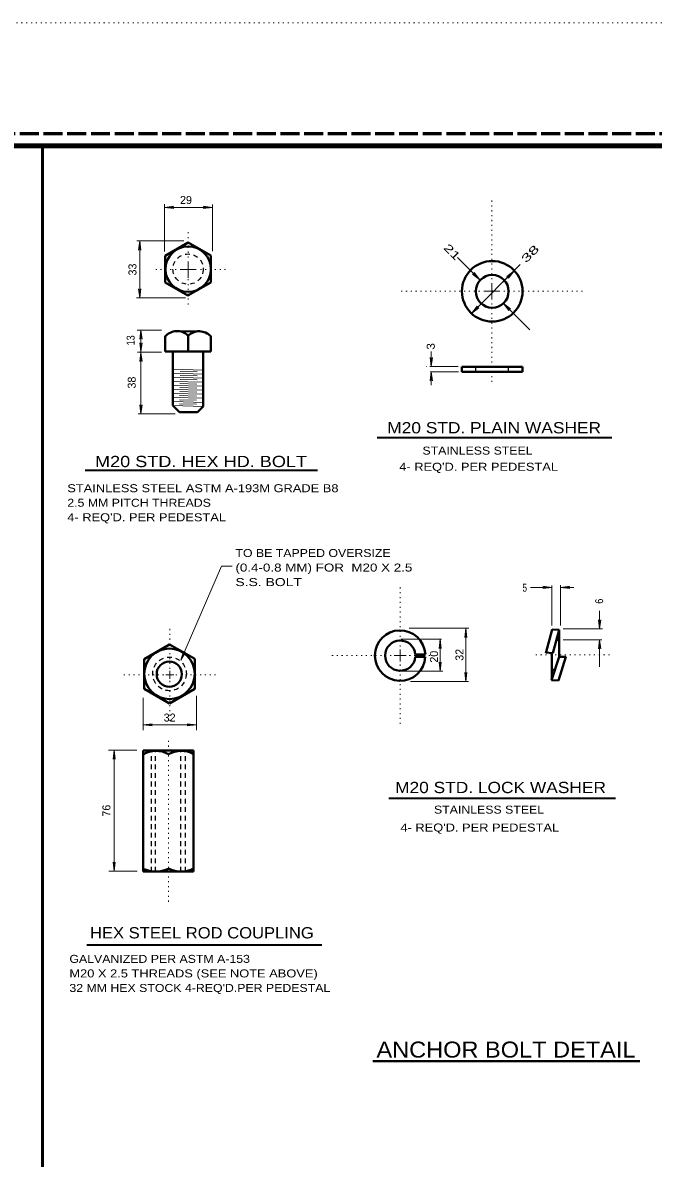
# Model space of a CAD drawing. Extents: x 312583 to 312854, y 144419 to 144597.
# Drawn here: x 312706.2 to 312766.1, y 144488.9 to 144596.8 of the extents above; entities that cross this region are included whole.
import ezdxf
from ezdxf.enums import TextEntityAlignment as Align

# ---------------------------------------------------------------- set-up
doc = ezdxf.new("R2010")
doc.units = 0
doc.header["$LTSCALE"] = 0.3
doc.header["$PDMODE"] = 32
doc.header["$PDSIZE"] = 0.15
for name, pattern in [('DOTTED', [1.5, 0.3, -1.2]), ('LONG_DASHED', [7.5, 6, -1.5]), ('SHORT_DASHED', [2.7, 1.5, -1.2])]:
    doc.linetypes.add(name, pattern=pattern)
for name, color, linetype, lineweight in [('1', 7, 'Continuous', 40), ('2', 7, 'Continuous', 13), ('62', 7, 'DOTTED', 13), ('63', 7, 'LONG_DASHED', 60)]:
    doc.layers.add(name, color=color, linetype=linetype, lineweight=lineweight)

msp = doc.modelspace()

# ---------------------------------------------------------------- linework, layer by layer
at = {"layer": '1', "linetype": 'DOTTED', "lineweight": 13}
for p, q in [((312721.9324, 144574.485), (312721.9324, 144577.176)), ((312720.7824, 144573.335), (312718.536, 144573.335)), ((312723.0824, 144573.335), (312725.7734, 144573.335)), ((312721.9324, 144572.4303), (312721.9324, 144569.7317)), ((312754.9401, 144536.7493), (312761.9935, 144536.7493)), ((312720.0558, 144513.3121), (312720.0558, 144528.8908))]:
    msp.add_line(p, q, dxfattribs=at)
at = {"layer": '1'}
for p, q in [((312719.7474, 144574.646), (312721.9324, 144575.9033)), ((312724.0714, 144574.669), (312721.9324, 144575.9033)), ((312719.7474, 144574.646), (312719.7474, 144572.1083)), ((312724.0714, 144574.669), (312724.0714, 144572.116)), ((312721.9094, 144570.8663), (312719.7474, 144572.1083)), ((312721.9094, 144570.8663), (312724.0714, 144572.116)), ((312722.9137, 144567.493), (312720.8284, 144567.47)), ((312719.7474, 144566.9947), (312719.7474, 144565.561)), ((312721.9247, 144565.5763), (312721.9247, 144567.056)), ((312724.0714, 144567.01), (312724.0714, 144565.561)), ((312719.7474, 144565.561), (312724.0714, 144565.561)), ((312720.4834, 144560.4243), (312720.4834, 144565.561)), ((312723.3584, 144560.3477), (312723.3584, 144565.561)), ((312747.9235, 144563.6439), (312747.9235, 144564.1193)), ((312747.9235, 144564.1193), (312753.6735, 144564.1193)), ((312753.6735, 144563.6439), (312753.6735, 144564.1193)), ((312747.9235, 144563.6439), (312753.6735, 144563.6439)), ((312720.4834, 144560.9993), (312720.4527, 144560.9687)), ((312720.4834, 144560.4243), (312721.0967, 144559.811)), ((312721.0967, 144559.811), (312722.8217, 144559.811)), ((312723.3584, 144560.3477), (312722.8217, 144559.811)), ((312756.5655, 144536.9179), (312757.1711, 144539.1259)), ((312757.1711, 144536.6036), (312757.1711, 144539.1259)), ((312756.9028, 144538.1906), (312757.1711, 144538.1906)), ((312717.7405, 144536.3428), (312720.1632, 144537.7458)), ((312722.5475, 144536.3658), (312720.1632, 144537.7458)), ((312755.8985, 144536.9639), (312756.5655, 144536.9179)), ((312717.7405, 144536.3428), (312717.7405, 144533.5215)), ((312722.5475, 144536.3658), (312722.5475, 144533.5291)), ((312744.4445, 144536.5576), (312743.4938, 144536.5576)), ((312744.4521, 144536.7953), (312743.5015, 144536.7953)), ((312756.4505, 144534.3573), (312756.4505, 144536.8566)), ((312757.1098, 144534.3036), (312757.7921, 144536.5806)), ((312756.4505, 144535.3616), (312756.7571, 144535.3386)), ((312756.4351, 144534.3496), (312757.1098, 144534.3036)), ((312720.1402, 144532.1415), (312717.7405, 144533.5215)), ((312720.1402, 144532.1415), (312722.5475, 144533.5291)), ((312717.6408, 144527.6641), (312717.6408, 144516.1641)), ((312717.6408, 144527.6641), (312722.4478, 144527.6641)), ((312722.4478, 144527.6641), (312722.4478, 144516.1641)), ((312717.6408, 144516.1641), (312722.4478, 144516.1641)), ((312739.4597, 144498.178), (312764.8218, 144498.178))]:
    msp.add_line(p, q, dxfattribs=at)
at = {"layer": '1', "lineweight": 13}
for p, q in [((312721.9324, 144573.335), (312721.9324, 144574.1017)), ((312721.9324, 144573.335), (312721.1657, 144573.335)), ((312721.9324, 144573.335), (312721.9324, 144572.5683)), ((312721.9324, 144573.335), (312722.699, 144573.335)), ((312744.5808, 144564.1423), (312744.5731, 144564.1423)), ((312720.468, 144563.491), (312723.3737, 144563.4143)), ((312720.4757, 144563.8743), (312723.3507, 144563.7977)), ((312720.491, 144563.1077), (312723.343, 144563.031)), ((312721.158, 144562.9007), (312722.768, 144562.8547)), ((312721.1657, 144563.284), (312722.7757, 144563.238)), ((312721.1734, 144563.6673), (312722.7834, 144563.6213)), ((312720.4757, 144562.7243), (312723.343, 144562.6477)), ((312720.5294, 144561.9577), (312723.3507, 144561.881)), ((312720.537, 144562.341), (312723.3584, 144562.2643)), ((312721.1274, 144561.7507), (312722.7374, 144561.7047)), ((312721.135, 144562.134), (312722.745, 144562.088)), ((312721.1427, 144562.5173), (312722.7527, 144562.4713)), ((312720.4987, 144560.8077), (312723.3737, 144560.731)), ((312720.5064, 144561.191), (312723.3814, 144561.1143)), ((312720.514, 144561.5743), (312723.389, 144561.4977)), ((312721.1044, 144560.984), (312722.7144, 144560.938)), ((312721.112, 144561.3673), (312722.722, 144561.3213)), ((312720.4834, 144560.4243), (312723.3584, 144560.3477)), ((312721.0967, 144560.6007), (312722.7067, 144560.5547)), ((312721.2442, 144536.2355), (312721.4801, 144537.0747)), ((312721.2442, 144536.2355), (312721.6767, 144536.9951)), ((312721.4801, 144537.0747), (312721.4735, 144536.7814)), ((312721.6767, 144536.9951), (312721.4735, 144536.7814))]:
    msp.add_line(p, q, dxfattribs=at)
at = {"layer": '1', "linetype": 'SHORT_DASHED', "lineweight": 25}
for p, q in [((312721.9247, 144570.8663), (312721.9017, 144570.874)), ((312749.2421, 144563.6439), (312749.2421, 144564.1193)), ((312752.3548, 144563.6439), (312752.3548, 144564.1193)), ((312720.1555, 144532.1415), (312720.1325, 144532.1568)), ((312718.4535, 144516.1641), (312718.4535, 144527.6641)), ((312718.8292, 144516.1641), (312718.8292, 144527.6641)), ((312721.2365, 144516.1641), (312721.2365, 144527.6641)), ((312721.6658, 144516.1641), (312721.6658, 144527.6641))]:
    msp.add_line(p, q, dxfattribs=at)
at = {"layer": '1', "lineweight": 35}
for p, q in [((312739.8748, 144557.4033), (312762.1627, 144557.4033)), ((312712.1367, 144554.2771), (312734.2119, 144554.2771)), ((312740.9745, 144523.1409), (312762.5182, 144523.1409)), ((312712.2913, 144509.2184), (312734.6146, 144509.2184))]:
    msp.add_line(p, q, dxfattribs=at)
at = {"layer": '1', "lineweight": 158}
msp.add_lwpolyline([(312616.5, 144423.1446), (312616.5, 144585.0846), (312849, 144585.0846)], dxfattribs=at)
at = {"layer": '1'}
for points in [[(312755.8908, 144536.9179), (312756.5041, 144539.1566), (312757.1711, 144539.1259)], [(312756.4351, 144534.3496), (312757.1635, 144536.5729), (312757.8228, 144536.5576)]]:
    msp.add_lwpolyline(points, dxfattribs=at)
for centre, radius in [((312721.9285, 144573.3848), 2.1562), ((312750.8023, 144571.2761), 2.875), ((312750.8023, 144571.2761), 1.5573), ((312720.1478, 144534.9513), 2.3958), ((312720.1325, 144534.9168), 1.1979)]:
    msp.add_circle(centre, radius, dxfattribs=at)
at = {"layer": '1', "linetype": 'SHORT_DASHED', "lineweight": 25}
for centre, radius in [((312721.9209, 144573.3848), 1.4375), ((312720.1546, 144534.9419), 1.5972)]:
    msp.add_circle(centre, radius, dxfattribs=at)
at = {"layer": '1'}
for centre, radius, start, end in [((312720.8664, 144566.0408), 1.4637, 43.91386, 141.2822), ((312722.9716, 144565.9716), 1.5099, 43.25022, 134.09484), ((312742.0563, 144536.6803), 2.3958, 2.66087, 356.97276), ((312742.064, 144536.6803), 1.4375, 4.43385, 354.95755), ((312718.8693, 144525.2575), 2.3801, 60.20304, 121.07217), ((312721.251, 144525.1939), 2.4434, 60.98127, 119.38719), ((312718.8464, 144518.9146), 2.7507, 243.73896, 296.26105), ((312721.2448, 144518.7408), 2.5691, 242.81753, 297.92176)]:
    msp.add_arc(centre, radius, start, end, dxfattribs=at)
at = {"layer": '2', "lineweight": 53}
msp.add_line((312708.0873, 144423.0846), (312708.0873, 144585.0846), dxfattribs=at)
at = {"layer": '2', "linetype": 'DOTTED'}
for p, q in [((312750.7601, 144572.4299), (312750.7601, 144580.0966)), ((312749.6101, 144571.2799), (312741.9435, 144571.2799)), ((312751.9101, 144571.2799), (312759.5768, 144571.2799)), ((312750.7601, 144570.1299), (312750.7601, 144562.4633)), ((312742.0678, 144537.5466), (312742.0678, 144543.2966)), ((312720.1785, 144535.4305), (312720.1785, 144539.2638)), ((312741.2015, 144536.6879), (312735.4515, 144536.6879)), ((312742.9265, 144536.6879), (312745.2341, 144536.6879)), ((312719.6035, 144534.8478), (312715.7702, 144534.8478)), ((312720.7535, 144534.8478), (312724.5868, 144534.8478)), ((312742.0678, 144535.8216), (312742.0678, 144530.0716)), ((312720.1785, 144534.2728), (312720.1785, 144530.4395))]:
    msp.add_line(p, q, dxfattribs=at)
at = {"layer": '2'}
for p, q in [((312719.686, 144575.0447), (312719.686, 144579.5603)), ((312719.686, 144579.246), (312720.5524, 144579.3533)), ((312719.686, 144579.246), (312724.2247, 144579.246)), ((312719.686, 144579.246), (312720.5524, 144579.1387)), ((312720.5524, 144579.3533), (312720.2764, 144579.246)), ((312720.5524, 144579.1387), (312720.2764, 144579.246)), ((312723.3584, 144579.3533), (312723.6344, 144579.246)), ((312724.2247, 144579.246), (312723.3584, 144579.3533)), ((312723.3584, 144579.3533), (312723.6344, 144579.246)), ((312724.2247, 144579.246), (312723.3584, 144579.3533)), ((312723.3584, 144579.1387), (312723.6344, 144579.246)), ((312724.2247, 144579.246), (312723.3584, 144579.1387)), ((312723.3584, 144579.1387), (312723.6344, 144579.246)), ((312724.2247, 144579.246), (312723.3584, 144579.1387)), ((312724.2247, 144575.0753), (312724.2247, 144579.5067)), ((312717.064, 144576.0567), (312721.526, 144576.0567)), ((312717.3247, 144576.0567), (312717.2174, 144575.1903)), ((312717.3247, 144570.6593), (312717.3247, 144576.0567)), ((312717.3247, 144576.0567), (312717.432, 144575.1903)), ((312717.2174, 144575.1903), (312717.3247, 144575.4663)), ((312717.432, 144575.1903), (312717.3247, 144575.4663)), ((312749.6255, 144572.3609), (312747.4941, 144574.4923)), ((312753.4588, 144573.8099), (312748.8281, 144569.1793)), ((312748.9355, 144572.8976), (312749.2115, 144572.7826)), ((312749.6255, 144572.3609), (312748.9355, 144572.8976)), ((312749.0888, 144573.0509), (312749.2115, 144572.7826)), ((312749.6255, 144572.3609), (312749.0888, 144573.0509)), ((312752.8761, 144573.2273), (312751.8028, 144572.1539)), ((312752.8761, 144573.2273), (312752.1861, 144572.6906)), ((312752.1861, 144572.6906), (312752.4545, 144572.8056)), ((312752.8761, 144573.2273), (312752.3395, 144572.5373)), ((312752.3395, 144572.5373), (312752.4545, 144572.8056)), ((312717.2174, 144571.5257), (312717.3247, 144571.2497)), ((312717.3247, 144570.6593), (312717.2174, 144571.5257)), ((312717.432, 144571.5257), (312717.3247, 144571.2497)), ((312717.3247, 144570.6593), (312717.432, 144571.5257)), ((312750.7601, 144571.2799), (312750.7601, 144572.0466)), ((312717.0104, 144570.6593), (312721.6794, 144570.6593)), ((312750.7601, 144571.2799), (312749.9935, 144571.2799)), ((312750.7601, 144571.2799), (312750.7601, 144570.5133)), ((312750.7601, 144571.2799), (312751.5268, 144571.2799)), ((312748.8281, 144569.1793), (312749.3648, 144569.8693)), ((312748.8281, 144569.1793), (312749.5181, 144569.7159)), ((312749.3648, 144569.8693), (312749.2421, 144569.5933)), ((312749.5181, 144569.7159), (312749.2421, 144569.5933)), ((312754.3635, 144567.6306), (312751.8488, 144570.1376)), ((312751.8488, 144570.1376), (312752.3855, 144569.4476)), ((312751.8488, 144570.1376), (312752.5388, 144569.6009)), ((312752.3855, 144569.4476), (312752.2705, 144569.7236)), ((312752.5388, 144569.6009), (312752.2705, 144569.7236)), ((312717.0717, 144567.585), (312719.3947, 144567.585)), ((312717.4397, 144567.585), (312717.3324, 144566.7187)), ((312717.4397, 144567.585), (312717.547, 144566.7187)), ((312717.4397, 144565.515), (312717.4397, 144567.585)), ((312717.3324, 144566.7187), (312717.4397, 144566.9947)), ((312717.3324, 144566.3813), (312717.4397, 144566.1053)), ((312717.4397, 144565.515), (312717.3324, 144566.3813)), ((312717.547, 144566.7187), (312717.4397, 144566.9947)), ((312717.547, 144566.3813), (312717.4397, 144566.1053)), ((312717.4397, 144565.515), (312717.547, 144566.3813)), ((312717.11, 144565.4843), (312719.3947, 144565.4843)), ((312717.4397, 144565.469), (312717.3324, 144564.6027)), ((312717.4397, 144559.6423), (312717.4397, 144565.469)), ((312717.4397, 144565.469), (312717.547, 144564.6027)), ((312744.9105, 144565.0009), (312745.0178, 144564.7249)), ((312745.0178, 144564.1346), (312744.9105, 144565.0009)), ((312745.0178, 144565.5453), (312745.0178, 144564.1346)), ((312745.1251, 144565.0009), (312745.0178, 144564.7249)), ((312745.0178, 144564.1346), (312745.1251, 144565.0009)), ((312717.3324, 144564.6027), (312717.4397, 144564.8787)), ((312717.547, 144564.6027), (312717.4397, 144564.8787)), ((312747.5631, 144564.1423), (312744.8875, 144564.1423)), ((312745.0178, 144563.6363), (312744.9105, 144562.7699)), ((312744.9105, 144562.7699), (312745.0178, 144563.0459)), ((312747.5861, 144563.6363), (312744.9181, 144563.6363)), ((312745.0178, 144563.6363), (312745.0178, 144562.3789)), ((312745.0178, 144563.6363), (312745.1251, 144562.7699)), ((312745.1251, 144562.7699), (312745.0178, 144563.0459)), ((312717.1867, 144559.6423), (312720.7057, 144559.6423)), ((312717.3324, 144560.5087), (312717.4397, 144560.2327)), ((312717.4397, 144559.6423), (312717.3324, 144560.5087)), ((312717.547, 144560.5087), (312717.4397, 144560.2327)), ((312717.4397, 144559.6423), (312717.547, 144560.5087)), ((312725.0965, 144545.1776), (312721.2442, 144536.2355)), ((312726.1085, 144545.1776), (312725.0965, 144545.1776)), ((312756.4658, 144543.1586), (312754.4493, 144543.1586)), ((312755.5995, 144543.2659), (312755.8755, 144543.1586)), ((312756.4658, 144543.1586), (312755.5995, 144543.2659)), ((312755.5995, 144543.0513), (312755.8755, 144543.1586)), ((312756.4658, 144543.1586), (312755.5995, 144543.0513)), ((312756.4581, 144539.5399), (312756.4581, 144543.3273)), ((312757.2861, 144539.5399), (312757.2861, 144543.3656)), ((312757.2938, 144543.1586), (312758.1601, 144543.2659)), ((312758.5665, 144543.1586), (312757.2938, 144543.1586)), ((312757.2938, 144543.1586), (312758.1601, 144543.0513)), ((312758.1601, 144543.2659), (312757.8841, 144543.1586)), ((312758.1601, 144543.0513), (312757.8841, 144543.1586)), ((312760.9968, 144539.2103), (312760.9968, 144540.9384)), ((312748.5768, 144539.2793), (312742.9111, 144539.2793)), ((312748.2931, 144539.2793), (312748.1858, 144538.4129)), ((312748.2931, 144534.2193), (312748.2931, 144539.2793)), ((312748.2931, 144539.2793), (312748.4005, 144538.4129)), ((312761.2881, 144539.2103), (312757.5315, 144539.2103)), ((312760.8895, 144540.0766), (312760.9968, 144539.8006)), ((312760.9968, 144539.2103), (312760.8895, 144540.0766)), ((312760.8895, 144540.0766), (312760.9968, 144539.8006)), ((312760.9968, 144539.2103), (312760.8895, 144540.0766)), ((312761.1041, 144540.0766), (312760.9968, 144539.8006)), ((312760.9968, 144539.2103), (312761.1041, 144540.0766)), ((312761.1041, 144540.0766), (312760.9968, 144539.8006)), ((312760.9968, 144539.2103), (312761.1041, 144540.0766)), ((312745.9931, 144538.2289), (312742.1291, 144538.2289)), ((312745.8551, 144538.2289), (312745.7478, 144537.3626)), ((312745.8551, 144535.1929), (312745.8551, 144538.2289)), ((312745.8551, 144538.2289), (312745.9625, 144537.3626)), ((312748.1858, 144538.4129), (312748.2931, 144538.6889)), ((312748.4005, 144538.4129), (312748.2931, 144538.6889)), ((312761.1961, 144538.1829), (312757.5315, 144538.1829)), ((312760.9968, 144538.1829), (312760.8895, 144537.3166)), ((312760.9968, 144535.6299), (312760.9968, 144538.1829)), ((312760.9968, 144538.1829), (312761.1041, 144537.3166)), ((312742.0678, 144536.6879), (312742.0678, 144537.2629)), ((312745.7478, 144537.3626), (312745.8551, 144537.6386)), ((312745.9625, 144537.3626), (312745.8551, 144537.6386)), ((312760.8895, 144537.3166), (312760.9968, 144537.5926)), ((312761.1041, 144537.3166), (312760.9968, 144537.5926)), ((312742.0678, 144536.6879), (312741.4851, 144536.6879)), ((312742.0678, 144536.6879), (312742.6428, 144536.6879)), ((312742.0678, 144536.6879), (312742.0678, 144536.1129)), ((312745.7478, 144536.0593), (312745.8551, 144535.7833)), ((312745.8551, 144535.1929), (312745.7478, 144536.0593)), ((312745.9625, 144536.0593), (312745.8551, 144535.7833)), ((312745.8551, 144535.1929), (312745.9625, 144536.0593)), ((312720.1785, 144534.8478), (312719.7952, 144534.8478)), ((312720.1785, 144534.8478), (312720.1785, 144535.2388)), ((312720.1785, 144534.8478), (312720.1785, 144534.4645)), ((312720.1785, 144534.8478), (312720.5618, 144534.8478)), ((312746.1005, 144535.1929), (312742.0525, 144535.1929)), ((312748.1858, 144535.0856), (312748.2931, 144534.8096)), ((312748.2931, 144534.2193), (312748.1858, 144535.0856)), ((312748.4005, 144535.0856), (312748.2931, 144534.8096)), ((312748.2931, 144534.2193), (312748.4005, 144535.0856)), ((312748.5615, 144534.2193), (312743.0261, 144534.2193)), ((312717.6562, 144532.6705), (312717.6562, 144529.5961)), ((312722.7085, 144532.8698), (312722.7085, 144529.5961)), ((312717.6562, 144530.1098), (312718.5225, 144530.2171)), ((312717.6562, 144530.1098), (312722.7085, 144530.1098)), ((312717.6562, 144530.1098), (312718.5225, 144530.0025)), ((312718.5225, 144530.2171), (312718.2465, 144530.1098)), ((312718.5225, 144530.0025), (312718.2465, 144530.1098)), ((312721.8422, 144530.2171), (312722.1182, 144530.1098)), ((312722.7085, 144530.1098), (312721.8422, 144530.2171)), ((312721.8422, 144530.0025), (312722.1182, 144530.1098)), ((312722.7085, 144530.1098), (312721.8422, 144530.0025)), ((312714.3672, 144527.7025), (312717.0582, 144527.7025)), ((312714.8962, 144527.7025), (312714.7888, 144526.8361)), ((312714.8962, 144527.7025), (312714.7888, 144526.8361)), ((312714.8962, 144516.2025), (312714.8962, 144527.7025)), ((312714.8962, 144527.7025), (312715.0035, 144526.8361)), ((312714.8962, 144527.7025), (312715.0035, 144526.8361)), ((312714.7888, 144526.8361), (312714.8962, 144527.1121)), ((312714.7888, 144526.8361), (312714.8962, 144527.1121)), ((312715.0035, 144526.8361), (312714.8962, 144527.1121)), ((312715.0035, 144526.8361), (312714.8962, 144527.1121)), ((312714.7888, 144517.0688), (312714.8962, 144516.7928)), ((312714.8962, 144516.2025), (312714.7888, 144517.0688)), ((312715.0035, 144517.0688), (312714.8962, 144516.7928)), ((312714.8962, 144516.2025), (312715.0035, 144517.0688)), ((312714.3978, 144516.2025), (312717.0965, 144516.2025))]:
    msp.add_line(p, q, dxfattribs=at)
msp.add_point((312750.8061, 144571.2799), dxfattribs=at)
at = {"layer": '62'}
msp.add_line((312601.2, 144596.7846), (312853.5, 144596.7846), dxfattribs=at)
at = {"layer": '63'}
msp.add_line((312851.75, 144586.2246), (312583.526, 144586.2246), dxfattribs=at)

# ---------------------------------------------------------------- texts
at = {"layer": '2'}
for s, p in [('29', (312721.1527, 144579.5709)), ('32', (312719.6009, 144530.4184))]:
    msp.add_text(s, height=0.76, dxfattribs=at).set_placement(p)
for s, rotation, width, p in [('21 ', 315, 1.5, (312746.1275, 144575.3471)), ('38', 45, 1.65, (312754.0059, 144573.9114)), ('13', 90, 0.85, (312716.8433, 144566.1365)), ('3 ', 90, 1.1, (312745.3431, 144565.7351)), ('6', 90, 0.85, (312761.3363, 144541.6081))]:
    msp.add_text(s, height=0.76, rotation=rotation, dxfattribs=dict(at, width=width)).set_placement(p)
for s, p in [('33', (312717.0136, 144572.778)), ('38', (312716.9457, 144562.0428)), ('20', (312745.649, 144536.0127)), ('32', (312748.0699, 144536.1922)), ('76', (312714.5403, 144521.3911))]:
    msp.add_text(s, height=0.76, rotation=90, dxfattribs=at).set_placement(p)
for s, height, width, p in [('M20 STD. PLAIN WASHER', 1.07, 1.15, (312750.9839, 144557.7862)), ('M20 STD. HEX HD. BOLT', 1.07, 1.2, (312723.1468, 144554.5819)), ('M20 STD. LOCK WASHER', 1.07, 1.15, (312751.5896, 144523.6235)), ('HEX STEEL ROD COUPLING', 1.07, 1.1, (312723.2264, 144509.8236)), ('ANCHOR BOLT DETAIL', 1.52, 1.1, (312752.1063, 144498.5067))]:
    msp.add_text(s, height=height, dxfattribs=dict(at, width=width)).set_placement(p, align=Align.CENTER)
for s, width, p in [('STAINLESS STEEL', 1.15, (312744.1745, 144555.7693)), ("4- REQ'D. PER PEDESTAL", 1.2, (312741.9741, 144554.2359)), ('STAINLESS STEEL ASTM A-193M GRADE B8', 1.2, (312710.4477, 144552.197)), ('2.5 MM PITCH THREADS', 1.15, (312710.4477, 144550.817)), ("4- REQ'D. PER PEDESTAL", 1.2, (312710.4477, 144549.437)), ('TO BE TAPPED OVERSIZE', 1.15, (312726.4151, 144546.043)), ('(0.4-0.8 MM) FOR  M20 X 2.5', 1.25, (312726.4151, 144544.663)), ('S.S. BOLT ', 1.3, (312726.4151, 144543.283)), ('5', 0.75, (312753.6761, 144542.7522)), ('STAINLESS STEEL', 1.15, (312745.2691, 144521.6756)), (" 4- REQ'D. PER PEDESTAL", 1.2, (312741.7424, 144519.9736)), ('GALVANIZED PER ASTM A-153', 1.15, (312710.6462, 144507.5)), ('M20 X 2.5 THREADS (SEE NOTE ABOVE)', 1.2, (312710.6462, 144506.12)), ("32 MM HEX STOCK 4-REQ'D.PER PEDESTAL", 1.15, (312710.6462, 144504.74))]:
    msp.add_text(s, height=0.76, dxfattribs=dict(at, width=width)).set_placement(p)

doc.saveas('drawing.dxf')
